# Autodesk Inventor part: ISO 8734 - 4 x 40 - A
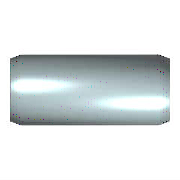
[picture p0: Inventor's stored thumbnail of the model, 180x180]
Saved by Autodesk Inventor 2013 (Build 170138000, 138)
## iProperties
IsCustomPart: 0
Created: 2012-02
Part Number: ISO 8734 - 4 x 40 - A
Material: Stahl
Description: Zylinderstift
Document SubType Name: Modeling
Standard: ISO 8734
Designer: rYan
Standards Organization: DIN
Language: de-DE
Size Designation: 4 x 40 - A
Categories: <MemberInstance><Categories><Category DisplayName="Verbindungselemente" InternalName="e4da775c-781d-43d5-af7c-5136215cf5a6" Mnemonic="FSTN"><Category DisplayNam
Density: 7.85 g/cm^3
Mass: 3.93564 g
Surface Area: 5.23591 cm^2
Volume: 0.501356 cm^3
Author: rYan
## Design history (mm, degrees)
sketch "Skizze"
  geometry: C1 r 2 at (0, 0); 1 further point
  constraints: 1 centre point, 1 coincident
  dimensions: "d1" = 4 diameter of C1 (= NND)
extrude "Körper" new body sketch "Skizze" distance "d2" = 40 (= NLG); taper "d3" = 0 deg
body "Solid1"
chamfer "Fase1" distance "d4" = 0.63 (= PHH); stored, may be unused: angle "d5" = 15 deg (= FAWI), second distance "d11" = 0.63 (= PHH)
chamfer "Fase2" distance "d8" = 0.63 (= PHH); stored, may be unused: angle "d9" = 15 deg (= FAWI), second distance "d12" = 0.63 (= PHH)
other parameters: "NND" = 4 [user parameter; used in 1 equation term], "NLG" = 40 [user parameter; used in 1 equation term], "PHH" = 0.63 [user parameter; used in 5 equation terms], "FAWI" = 15 deg [user parameter; used in 2 equation terms], "d13" = 0, "d15" = 0, "d16" = 0, "PHH2" = 0.63 (= PHH) [user parameter], "FAWI2" = 15 deg [user parameter]
